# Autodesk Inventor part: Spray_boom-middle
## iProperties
Created: 2007-04
Part Number: Spray_boom-middle
Material: Steel, Mild
Document SubType Name: Sheet Metal
Designer: Admin
Density: 1 g/cm^3
Sheet Metal Rule: Default
Author: Admin
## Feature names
1. Bend3
2. Plate1
3. Plate2
4. Bend1
5. Plate3
6. Bend2
7. Cut1
